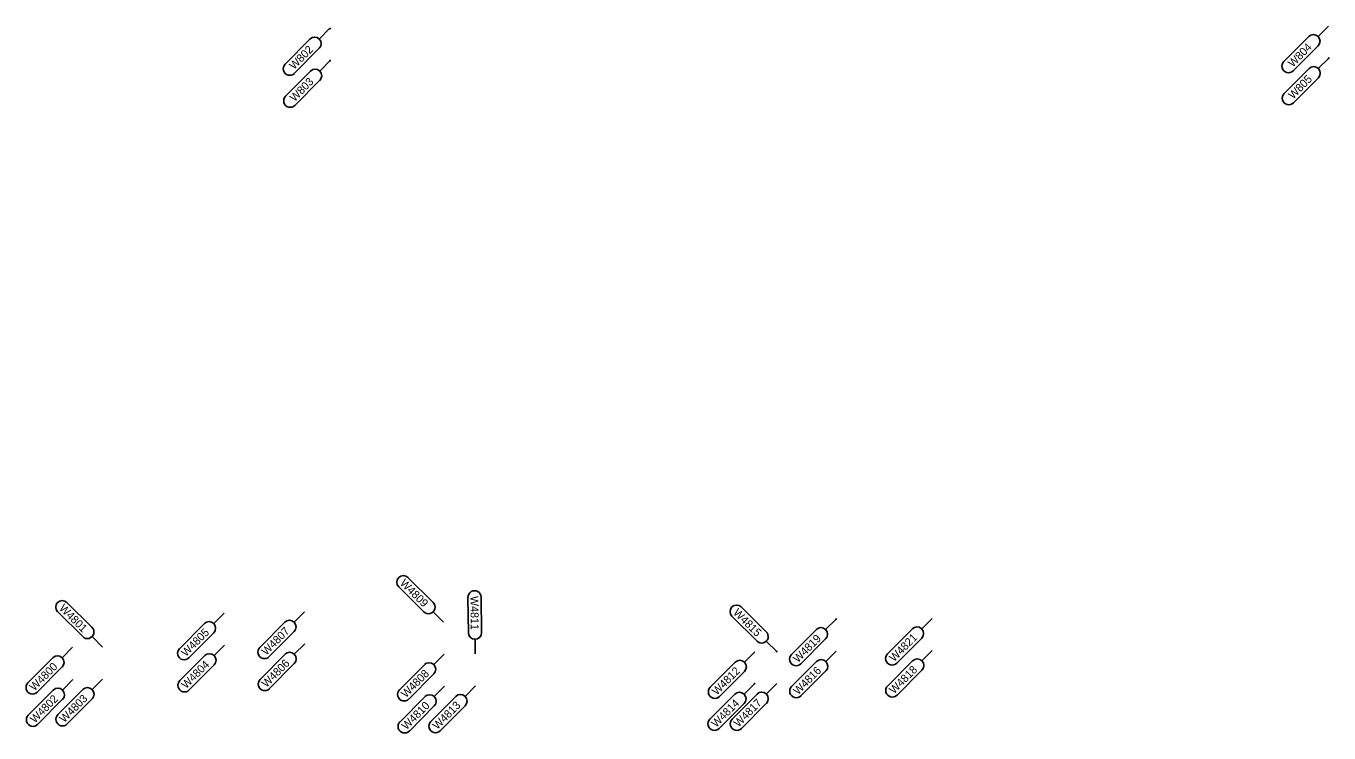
# Model space of a CAD drawing. Extents: x 12479652 to 12487250, y 9842710 to 9846560.
# Drawn here: x 12481129.9 to 12481333.5, y 9842723.3 to 9842833.7 of the extents above; entities that cross this region are included whole.
import ezdxf

# ---------------------------------------------------------------- set-up
doc = ezdxf.new("R2010")
doc.units = 0
doc.layers.add('_CIVIL_CONSTRUCTION', color=7, linetype='Continuous')
doc.layers.add('TextAlignmentLrg', color=7, linetype='Continuous')

msp = doc.modelspace()

# ---------------------------------------------------------------- linework, layer by layer
at = {"layer": '_CIVIL_CONSTRUCTION'}
for p, q in [((12481177.37, 9842833.32), (12481175.75, 9842831.69)), ((12481333.39, 9842833.71), (12481331.77, 9842832.08)), ((12481170.41, 9842827.77), (12481174.3, 9842831.68)), ((12481326.43, 9842828.16), (12481330.32, 9842832.08)), ((12481331.78, 9842830.63), (12481327.89, 9842826.72)), ((12481175.75, 9842830.24), (12481171.86, 9842826.33)), ((12481333.43, 9842828.71), (12481331.81, 9842827.08)), ((12481170.49, 9842822.77), (12481174.38, 9842826.68)), ((12481177.45, 9842828.32), (12481175.83, 9842826.69)), ((12481326.47, 9842823.16), (12481330.36, 9842827.08)), ((12481175.83, 9842825.24), (12481171.94, 9842821.33)), ((12481331.82, 9842825.63), (12481327.93, 9842821.72)), ((12481189.61, 9842747.58), (12481193.53, 9842743.69)), ((12481192.08, 9842742.24), (12481188.17, 9842746.13)), ((12481136.33, 9842743.69), (12481140.25, 9842739.8)), ((12481199.04, 9842738.96), (12481198.97, 9842744.48)), ((12481201.03, 9842744.5), (12481201.09, 9842738.99)), ((12481138.8, 9842738.35), (12481134.89, 9842742.24)), ((12481160.88, 9842742.02), (12481159.26, 9842740.39)), ((12481173.43, 9842742.23), (12481171.81, 9842740.59)), ((12481195.16, 9842740.62), (12481193.53, 9842742.24)), ((12481244.13, 9842737.64), (12481240.21, 9842741.53)), ((12481241.66, 9842742.99), (12481245.57, 9842739.1)), ((12481256.47, 9842741.09), (12481254.85, 9842739.46)), ((12481271.47, 9842741.2), (12481269.85, 9842739.57)), ((12481153.92, 9842736.47), (12481157.8, 9842740.39)), ((12481166.47, 9842736.68), (12481170.36, 9842740.59)), ((12481171.82, 9842739.14), (12481167.93, 9842735.23)), ((12481249.51, 9842735.54), (12481253.4, 9842739.45)), ((12481264.51, 9842735.66), (12481268.4, 9842739.57)), ((12481141.88, 9842736.73), (12481140.25, 9842738.35)), ((12481159.26, 9842738.94), (12481155.37, 9842735.03)), ((12481160.93, 9842737.02), (12481159.31, 9842735.39)), ((12481173.47, 9842737.22), (12481171.85, 9842735.59)), ((12481200.11, 9842735.65), (12481200.08, 9842737.95)), ((12481247.21, 9842736.03), (12481245.58, 9842737.65)), ((12481254.85, 9842738), (12481250.96, 9842734.09)), ((12481269.85, 9842738.12), (12481265.96, 9842734.21)), ((12481130.25, 9842731.14), (12481134.14, 9842735.06)), ((12481137.21, 9842736.69), (12481135.59, 9842735.06)), ((12481153.97, 9842731.48), (12481157.86, 9842735.39)), ((12481166.51, 9842731.68), (12481170.4, 9842735.59)), ((12481195.25, 9842735.61), (12481193.63, 9842733.98)), ((12481243.79, 9842735.99), (12481242.17, 9842734.36)), ((12481256.51, 9842736.09), (12481254.88, 9842734.46)), ((12481271.51, 9842736.2), (12481269.88, 9842734.57)), ((12481135.59, 9842733.61), (12481131.7, 9842729.7)), ((12481159.32, 9842733.94), (12481155.43, 9842730.03)), ((12481171.85, 9842734.14), (12481167.96, 9842730.23)), ((12481188.29, 9842730.06), (12481192.18, 9842733.97)), ((12481236.83, 9842730.44), (12481240.72, 9842734.35)), ((12481249.54, 9842730.54), (12481253.43, 9842734.45)), ((12481254.89, 9842733), (12481251, 9842729.09)), ((12481264.54, 9842730.66), (12481268.43, 9842734.57)), ((12481269.89, 9842733.12), (12481266, 9842729.21)), ((12481137.27, 9842731.64), (12481135.64, 9842730.01)), ((12481141.88, 9842731.72), (12481140.26, 9842730.09)), ((12481193.63, 9842732.53), (12481189.74, 9842728.61)), ((12481242.18, 9842732.91), (12481238.29, 9842728.99)), ((12481243.72, 9842730.99), (12481242.1, 9842729.36)), ((12481247.2, 9842731.01), (12481245.58, 9842729.38)), ((12481130.3, 9842726.09), (12481134.19, 9842730.01)), ((12481134.92, 9842726.17), (12481138.81, 9842730.08)), ((12481188.37, 9842725.06), (12481192.26, 9842728.97)), ((12481193.19, 9842725.1), (12481197.08, 9842729.01)), ((12481195.33, 9842730.61), (12481193.71, 9842728.98)), ((12481200.15, 9842730.65), (12481198.53, 9842729.01)), ((12481236.76, 9842725.44), (12481240.65, 9842729.35)), ((12481240.24, 9842725.47), (12481244.13, 9842729.38)), ((12481135.65, 9842728.56), (12481131.76, 9842724.65)), ((12481140.26, 9842728.63), (12481136.37, 9842724.72)), ((12481193.71, 9842727.53), (12481189.82, 9842723.61)), ((12481198.53, 9842727.56), (12481194.64, 9842723.65)), ((12481242.1, 9842727.9), (12481238.22, 9842723.99)), ((12481245.58, 9842727.93), (12481241.69, 9842724.02))]:
    msp.add_line(p, q, dxfattribs=at)
for centre, start, end in [((12481175.02, 9842830.96), 315.1702, 135.1702), ((12481331.05, 9842831.35), 315.1702, 135.1702), ((12481171.14, 9842827.05), 135.1702, 315.1702), ((12481175.11, 9842825.96), 315.1702, 135.1702), ((12481327.16, 9842827.44), 135.1702, 315.1702), ((12481331.09, 9842826.35), 315.1702, 135.1702), ((12481171.22, 9842822.05), 135.1702, 315.1702), ((12481327.2, 9842822.44), 135.1702, 315.1702), ((12481188.89, 9842746.85), 45.1702, 225.1702), ((12481200, 9842744.49), 0.6845, 180.6845), ((12481135.61, 9842742.96), 45.1702, 225.1702), ((12481192.8, 9842742.96), 225.1702, 45.1702), ((12481240.94, 9842742.26), 45.1702, 225.1702), ((12481139.52, 9842739.08), 225.1702, 45.1702), ((12481158.53, 9842739.66), 315.1702, 135.1702), ((12481171.09, 9842739.87), 315.1702, 135.1702), ((12481244.85, 9842738.37), 225.1702, 45.1702), ((12481254.12, 9842738.73), 315.1702, 135.1702), ((12481269.12, 9842738.85), 315.1702, 135.1702), ((12481200.07, 9842738.97), 180.6845, 0.6845), ((12481134.86, 9842734.33), 315.1702, 135.1702), ((12481154.64, 9842735.75), 135.1702, 315.1702), ((12481158.59, 9842734.66), 315.1702, 135.1702), ((12481167.2, 9842735.95), 135.1702, 315.1702), ((12481171.12, 9842734.87), 315.1702, 135.1702), ((12481250.23, 9842734.82), 135.1702, 315.1702), ((12481265.23, 9842734.93), 135.1702, 315.1702), ((12481192.91, 9842733.25), 315.1702, 135.1702), ((12481241.45, 9842733.63), 315.1702, 135.1702), ((12481254.16, 9842733.73), 315.1702, 135.1702), ((12481269.16, 9842733.85), 315.1702, 135.1702), ((12481130.97, 9842730.42), 135.1702, 315.1702), ((12481154.7, 9842730.75), 135.1702, 315.1702), ((12481167.23, 9842730.95), 135.1702, 315.1702), ((12481134.92, 9842729.28), 315.1702, 135.1702), ((12481139.54, 9842729.36), 315.1702, 135.1702), ((12481189.02, 9842729.34), 135.1702, 315.1702), ((12481192.98, 9842728.25), 315.1702, 135.1702), ((12481197.81, 9842728.29), 315.1702, 135.1702), ((12481237.56, 9842729.72), 135.1702, 315.1702), ((12481241.38, 9842728.63), 315.1702, 135.1702), ((12481244.86, 9842728.66), 315.1702, 135.1702), ((12481250.27, 9842729.82), 135.1702, 315.1702), ((12481265.27, 9842729.93), 135.1702, 315.1702), ((12481131.03, 9842725.37), 135.1702, 315.1702), ((12481135.65, 9842725.44), 135.1702, 315.1702), ((12481189.09, 9842724.34), 135.1702, 315.1702), ((12481193.92, 9842724.37), 135.1702, 315.1702), ((12481237.49, 9842724.72), 135.1702, 315.1702), ((12481240.97, 9842724.74), 135.1702, 315.1702)]:
    msp.add_arc(centre, 1.03, start, end, dxfattribs=at)
at = {"layer": 'TextAlignmentLrg'}
for centre in [(12481177.45, 9842833.31), (12481333.42, 9842828.7), (12481177.44, 9842828.31), (12481256.48, 9842741.09), (12481247.21, 9842736.02), (12481243.73, 9842730.99)]:
    msp.add_circle(centre, 0.05, dxfattribs=at)

# ---------------------------------------------------------------- texts
at = {"layer": '_CIVIL_CONSTRUCTION'}
for s, rotation, p in [('W802', 45.1702, (12481171.82, 9842826.83)), ('W804', 45.1702, (12481327.82, 9842827.2)), ('W803', 45.1702, (12481171.89, 9842821.82)), ('W805', 45.1702, (12481327.87, 9842822.22)), ('W4809', 315.1702, (12481188.26, 9842746.58)), ('W4801', 315.1702, (12481135.02, 9842742.66)), ('W4811', 270.6845, (12481199.36, 9842744.69)), ('W4815', 315.1702, (12481240.32, 9842741.98)), ('W4805', 45.1702, (12481154.93, 9842735.14)), ('W4807', 45.1702, (12481167.48, 9842735.34)), ('W4819', 45.1702, (12481250.51, 9842734.19)), ('W4821', 45.1702, (12481265.54, 9842734.34)), ('W4800', 45.1702, (12481131.24, 9842729.79)), ('W4804', 45.1702, (12481154.96, 9842730.12)), ('W4806', 45.1702, (12481167.5, 9842730.32)), ('W4808', 45.1702, (12481189.29, 9842728.71)), ('W4812', 45.1702, (12481237.85, 9842729.11)), ('W4816', 45.1702, (12481250.54, 9842729.18)), ('W4818', 45.1702, (12481265.54, 9842729.31)), ('W4802', 45.1702, (12481131.32, 9842724.76)), ('W4803', 45.1702, (12481135.93, 9842724.82)), ('W4810', 45.1702, (12481189.37, 9842723.71)), ('W4813', 45.1702, (12481194.2, 9842723.75)), ('W4814', 45.1702, (12481237.75, 9842724.08)), ('W4817', 45.1702, (12481241.25, 9842724.13))]:
    msp.add_text(s, height=1.25, rotation=rotation, dxfattribs=at).set_placement(p)

doc.saveas('drawing.dxf')
